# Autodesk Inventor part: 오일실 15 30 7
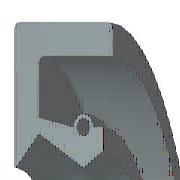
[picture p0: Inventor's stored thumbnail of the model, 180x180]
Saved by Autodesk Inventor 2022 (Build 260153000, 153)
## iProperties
Created: 2012-02
Part Number: 오일실 15 30 7
Material: 고무
Description: 오일-실
Document SubType Name: Modeling
Standard: KS B 2804
Designer: mduedu
Standards Organization: KS
Language: ko-KR
Size Designation: D - 15 30 7
Categories: <MemberInstance><Categories><Category DisplayName="샤프트 부품" InternalName="7f7aeb1f-a693-4053-b835-cee3144e0d98" Mnemonic="SHFT"><Category DisplayName="실링" Intern
Density: 0.93 g/cm^3
Appearance: 고무 - 검은색 - 버전 1.1
IsCustomPart: 1
Author: mduedu
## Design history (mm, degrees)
revolve "본체" stored, may be unused: angle "d17" = 90 deg
revolve "스프링1" stored, may be unused: angle "d18" = 90 deg
body "Solid1"
sketch "스케치1"
  geometry: L1 (0, 15)-(7, 15); L2 (7, 13.25)-(1.75, 13.25); L3 (1.75, 9.25)-(4.9, 7.5); L4 (4.9, 7.5)-(0, 7.5); L5 (0, 0)-(9.586, 0) reference; L6 (4.9, 7.5)-(6.3, 8.375); L7 (0, 18)-(0, -3) reference; L8 (-1.941, 0)-(11.507, 0) reference; L9 (4.2, 9.6)-(1.75, 10.09); L10 (1.75, 10.09)-(1.75, 13.25); L11 (0, 15)-(0, 7.588); L12 (4.9, 7.5)-(0, 7.5); L13 (1.75, 9.25)-(0.152, 7.528); L14 (7, 15)-(7, 13.25); L15 (5.6, 9.6)-(6.3, 9.6); L16 (6.3, 9.6)-(6.3, 8.375); C1 r 0.455 at (4.9, 9.6); A1 r 0.7 centre (4.9, 9.6) between (5.6, 9.6) and (4.2, 9.6); A2 r 0.088 centre (0.088, 7.588) between (0, 7.588) and (0.152, 7.528); 1 further point
  constraints: 28 end point, 5 horizontal alignment, 5 point on line, 4 point on circle, 4 vertical alignment, 3 centre point, 3 tangent, 2 collinear, 2 horizontal, 2 perpendicular, 1 coincident, 1 parallel
  dimensions: "d0" = 30 diameter of L1 L5 (= SD2); "d1" = 1.75 distance of L1.end L2.start (= SD); "d2" = 0.91 diameter of C1 (= SPDI); "d3" = 1.4 diameter of A1 (= SPDA); "d4" = 15 diameter of L3.end L5 (= NND); "d5" = 18.5 diameter of L3.start L5 (= TKDM); "d7" = 20.18 diameter of L9.end L5 (= TKDM + 0.24 x SWDT); "d8" = 1.75 distance between parallel lines of L11 L10 (= SD); "d9" = 4.9 distance from line of L11 C1.centre (= SPDST); "d10" = 19.2 diameter of C1.centre L5 (= HLDM); "d11" = 0.0875 radius of A2 (= 0.25 x LAB); "d12" = 6.3 distance between parallel lines of L11 L16 (= SDI); "d13" = 16.75 diameter of L6.end L5 (= ABDM); "d14" = 7 distance from line of L11 L1.end (= SWDT)
fillet "모깎기1" dims "d6" = 0.3 (= RR)
other parameters: "SD2" = 30 [user parameter; used in 1 equation term], "SWDT" = 7 [user parameter; used in 2 equation terms], "RR" = 0.3 [user parameter; used in 1 equation term], "SD" = 1.75 [user parameter; used in 2 equation terms], "NND" = 15 [user parameter; used in 1 equation term], "SPDA" = 1.4 [user parameter; used in 1 equation term], "SPDI" = 0.91 [user parameter; used in 1 equation term], "TKDM" = 18.5 [user parameter; used in 2 equation terms], "HLDM" = 19.2 [user parameter; used in 1 equation term], "ABDM" = 16.75 [user parameter; used in 1 equation term], "SDI" = 6.3 [user parameter; used in 1 equation term], "SPDST" = 4.9 [user parameter; used in 1 equation term], "LAB" = 0.35 [user parameter; used in 1 equation term], "d15" = 0, "d16" = 0, "d19" = 0
